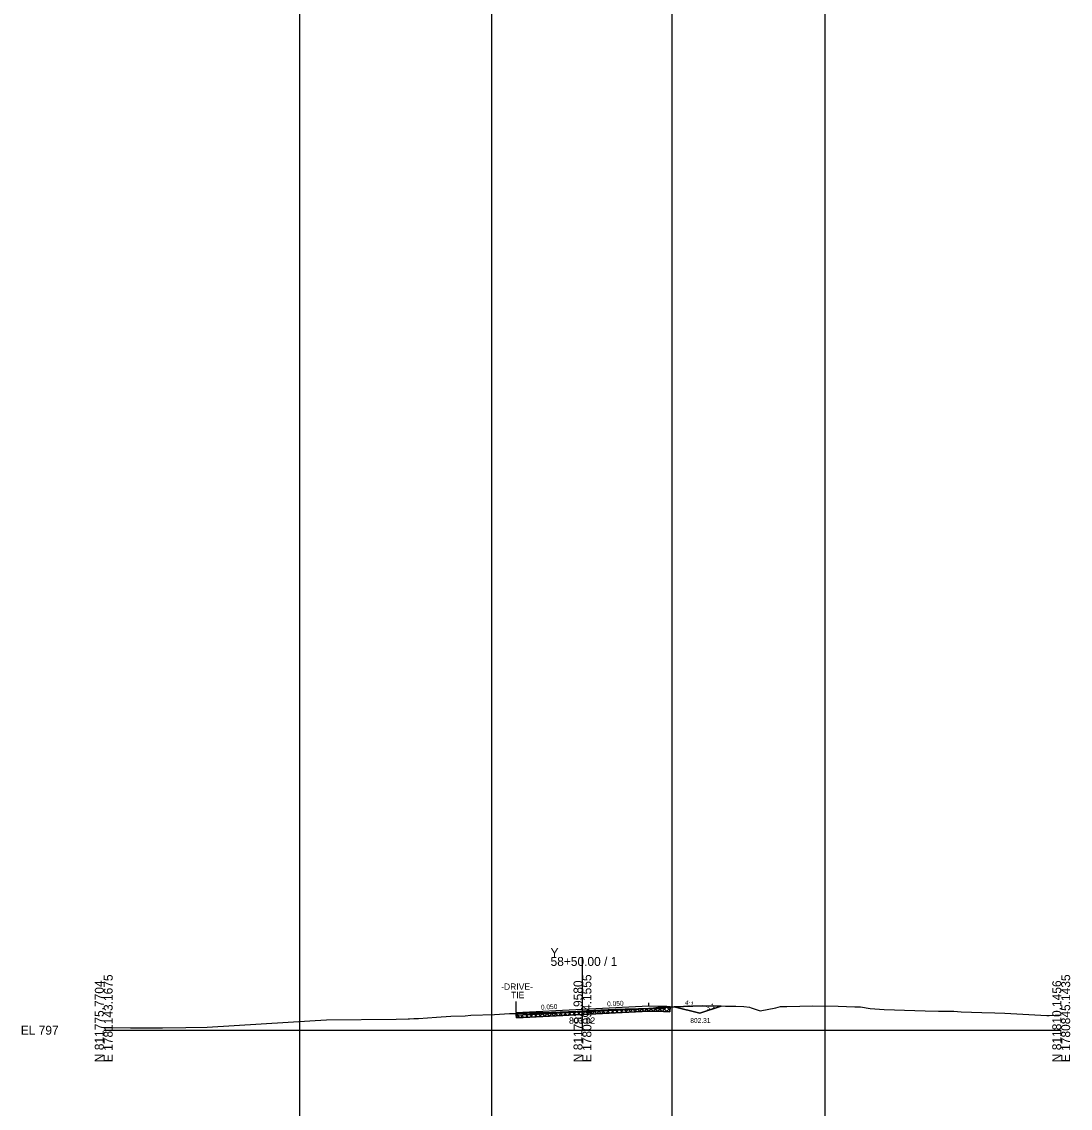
# Model space of a CAD drawing. Extents: x -12583 to 5303, y -44 to 25667.
# Drawn here: x 3974.3 to 4302.8, y 8975.6 to 9315.9 of the extents above; entities that cross this region are included whole.
import ezdxf

# ---------------------------------------------------------------- set-up
doc = ezdxf.new("R2010")
doc.units = 0
for name, color, linetype in [('Exist Cross Section Cell', 7, 'Continuous'), ('Exist XS Center Line Elevation Label', 7, 'Continuous'), ('Exist XS Ground Line', 7, 'Continuous'), ('Prop CMT Shallow Undercut', 7, 'Continuous'), ('Prop XS Ditch Slope Text', 7, 'Continuous'), ('Prop XS Ditch Standard Text', 7, 'Continuous'), ('Prop XS Dump Level', 7, 'Continuous'), ('Prop XS Earthwork Shape', 7, 'Continuous'), ('Prop XS Earthwork Undercut', 7, 'Continuous'), ('Prop XS EOT Tick Mark', 7, 'Continuous'), ('Prop XS Exc Vertical Line 1', 7, 'Continuous'), ('Prop XS Exc Vertical Line 2', 7, 'Continuous'), ('Prop XS Finish Grade', 7, 'Continuous'), ('Prop XS Finish Grade Earthwork', 7, 'Continuous'), ('Prop XS Finish Grade Paved Shoulder', 7, 'Continuous'), ('Prop XS Finish Grade Pavement', 7, 'Continuous'), ('Prop XS Label Text', 7, 'Continuous'), ('Prop XS Pvmt Edge Slope', 7, 'Continuous'), ('Prop XS SE Text', 7, 'Continuous'), ('Prop XS Side Slope Text', 7, 'Continuous'), ('Prop XS Subgrade Earthwork', 7, 'Continuous'), ('Prop XS Undercut Exc Hatch', 7, 'Continuous'), ('Scratch_Level_1', 7, 'Continuous'), ('Scratch_Level_2', 7, 'Continuous'), ('Scratch_Level_3', 7, 'Continuous'), ('Scratch_Level_4', 7, 'Continuous'), ('Scratch_Level_6', 7, 'Continuous')]:
    doc.layers.add(name, color=color, linetype=linetype)

msp = doc.modelspace()

# ---------------------------------------------------------------- linework, layer by layer
at = {"layer": 'Exist Cross Section Cell'}
for p, q in [((4150, 9000), (4150, 9022.94)), ((4000, 9000), (4150, 9000)), ((4150, 9000), (4300, 9000))]:
    msp.add_line(p, q, dxfattribs=at)
at = {"layer": 'Exist XS Ground Line'}
for p, q in [((4140.33, 9005.57), (4148.34, 9005.9)), ((4148.34, 9005.9), (4150, 9006.02)), ((4150, 9006.02), (4151.27, 9006.11)), ((4151.27, 9006.11), (4160.25, 9006.46)), ((4160.25, 9006.46), (4162.27, 9006.51)), ((4162.27, 9006.51), (4163.41, 9006.62)), ((4163.41, 9006.62), (4169.21, 9006.71)), ((4169.21, 9006.71), (4171.58, 9006.85)), ((4171.58, 9006.85), (4174.96, 9007.28)), ((4174.96, 9007.28), (4176.48, 9007.46)), ((4176.48, 9007.46), (4176.52, 9007.22)), ((4176.52, 9007.22), (4178.69, 9007.3)), ((4178.69, 9007.3), (4187.52, 9007.61)), ((4187.52, 9007.61), (4194.8, 9007.55)), ((4194.8, 9007.55), (4198.09, 9007.5)), ((4198.09, 9007.5), (4200.56, 9007.4)), ((4200.56, 9007.4), (4202.3, 9007.24)), ((4202.3, 9007.24), (4202.82, 9007.03)), ((4202.82, 9007.03), (4205.63, 9006.07)), ((4205.63, 9006.07), (4210.54, 9007.05)), ((4210.54, 9007.05), (4212.06, 9007.42)), ((4212.06, 9007.42), (4214.06, 9007.45)), ((4214.06, 9007.45), (4222.22, 9007.65)), ((4222.22, 9007.65), (4230.1, 9007.54)), ((4230.1, 9007.54), (4235.31, 9007.33)), ((4235.31, 9007.33), (4237.16, 9007.31)), ((4237.16, 9007.31), (4240.1, 9006.85)), ((4240.1, 9006.85), (4244.56, 9006.52)), ((4244.56, 9006.52), (4254.13, 9006.21)), ((4254.13, 9006.21), (4257.35, 9006.04)), ((4257.35, 9006.04), (4261.58, 9005.93)), ((4261.58, 9005.93), (4266.38, 9006.02)), ((4266.38, 9006.02), (4268.61, 9005.81)), ((4268.61, 9005.81), (4275.14, 9005.59)), ((4032.37, 9000.92), (4066.24, 9003.07)), ((4066.24, 9003.07), (4069.75, 9003.24)), ((4069.75, 9003.24), (4091.59, 9003.52)), ((4091.59, 9003.52), (4095.41, 9003.57)), ((4095.41, 9003.57), (4095.81, 9003.59)), ((4095.81, 9003.59), (4097.14, 9003.65)), ((4097.14, 9003.65), (4098.59, 9003.71)), ((4098.59, 9003.71), (4104.23, 9004.13)), ((4104.23, 9004.13), (4108.74, 9004.41)), ((4108.74, 9004.41), (4113.23, 9004.51)), ((4113.23, 9004.51), (4114.98, 9004.67)), ((4114.98, 9004.67), (4122.4, 9004.93)), ((4122.4, 9004.93), (4123.96, 9005)), ((4123.96, 9005), (4127.14, 9005.21)), ((4127.14, 9005.21), (4129.88, 9005.23)), ((4129.88, 9005.23), (4135.52, 9005.43)), ((4135.52, 9005.43), (4140.33, 9005.57)), ((4275.14, 9005.59), (4279.21, 9005.49)), ((4279.21, 9005.49), (4282.32, 9005.34)), ((4282.32, 9005.34), (4295.49, 9004.62)), ((4295.49, 9004.62), (4295.94, 9004.62)), ((4295.94, 9004.62), (4296.27, 9004.61)), ((4296.27, 9004.61), (4300, 9004.83)), ((4000, 9000.84), (4008.37, 9000.75)), ((4008.37, 9000.75), (4016.58, 9000.75)), ((4016.58, 9000.75), (4017.64, 9000.74)), ((4017.64, 9000.74), (4018.45, 9000.75)), ((4018.45, 9000.75), (4025.75, 9000.84)), ((4025.75, 9000.84), (4032.37, 9000.92))]:
    msp.add_line(p, q, dxfattribs=at)
at = {"layer": 'Prop CMT Shallow Undercut'}
msp.add_lwpolyline([(4176.18, 9007.43), (4176.48, 9007.46), (4176.52, 9007.22), (4177.45, 9007.25), (4177.35, 9005.78), (4175.38, 9005.92), (4170.77, 9005.97), (4150.05, 9004.93), (4129.3, 9003.89), (4129.25, 9004.77), (4150.04, 9005.8), (4167.58, 9006.68), (4169.21, 9006.71), (4171.38, 9006.84), (4175.55, 9006.79)], close=True, dxfattribs=at)
at = {"layer": 'Prop XS Dump Level'}
for p, q in [((4129.25, 9005.56), (4150, 9006.6)), ((4150, 9006.6), (4170.75, 9007.63))]:
    msp.add_line(p, q, dxfattribs=at)
at = {"layer": 'Prop XS Earthwork Shape'}
for points in [[(4151.27, 9006.11), (4160.25, 9006.46), (4162.27, 9006.51), (4163.41, 9006.62), (4167.58, 9006.68), (4150.04, 9005.8), (4129.25, 9004.77), (4129.25, 9005.22), (4129.88, 9005.23), (4135.52, 9005.43), (4140.33, 9005.57), (4148.34, 9005.9), (4150, 9006.02)], [(4167.58, 9006.68), (4169.21, 9006.71), (4171.38, 9006.84), (4170.77, 9006.84)], [(4171.38, 9006.84), (4175.55, 9006.79), (4176.18, 9007.43), (4174.96, 9007.28), (4171.58, 9006.85)], [(4176.18, 9007.43), (4176.24, 9007.49), (4176.48, 9007.46)], [(4178.75, 9007.31), (4178.78, 9007.31), (4178.69, 9007.3), (4176.52, 9007.22), (4176.48, 9007.46)], [(4178.78, 9007.31), (4186.75, 9005.31), (4193.5, 9007.56), (4187.52, 9007.61)]]:
    msp.add_lwpolyline(points, close=True, dxfattribs=at)
at = {"layer": 'Prop XS Earthwork Undercut'}
for p, q in [((4129.25, 9005.56), (4129.25, 9008.99)), ((4170.77, 9005.97), (4150.05, 9004.93)), ((4170.77, 9005.97), (4175.38, 9005.92)), ((4175.38, 9005.92), (4177.35, 9005.78)), ((4177.45, 9007.25), (4177.35, 9005.78)), ((4129.26, 9004.77), (4129.3, 9003.89)), ((4150.05, 9004.93), (4129.3, 9003.89))]:
    msp.add_line(p, q, dxfattribs=at)
at = {"layer": 'Prop XS EOT Tick Mark'}
for p, q in [((4129.25, 9005.56), (4129.25, 9006.56)), ((4170.75, 9007.63), (4170.75, 9008.63))]:
    msp.add_line(p, q, dxfattribs=at)
at = {"layer": 'Prop XS Exc Vertical Line 1'}
msp.add_line((4121.63, 6478.95), (4121.63, 9656.26), dxfattribs=at)
at = {"layer": 'Prop XS Exc Vertical Line 2'}
msp.add_line((4178.09, 6478.95), (4178.09, 9642.11), dxfattribs=at)
at = {"layer": 'Prop XS Finish Grade'}
msp.add_line((4174.75, 9007.59), (4176.24, 9007.49), dxfattribs=at)
at = {"layer": 'Prop XS Finish Grade Earthwork'}
for p, q in [((4176.24, 9007.49), (4178.75, 9007.31)), ((4178.75, 9007.31), (4186.75, 9005.31)), ((4186.75, 9005.31), (4193.5, 9007.56))]:
    msp.add_line(p, q, dxfattribs=at)
at = {"layer": 'Prop XS Finish Grade Paved Shoulder'}
msp.add_line((4170.75, 9007.63), (4174.75, 9007.59), dxfattribs=at)
at = {"layer": 'Prop XS Finish Grade Pavement'}
for p, q in [((4129.25, 9005.56), (4150, 9006.6)), ((4150, 9006.6), (4170.75, 9007.63)), ((4129.25, 9005.56), (4129.25, 9005.22))]:
    msp.add_line(p, q, dxfattribs=at)
at = {"layer": 'Prop XS Pvmt Edge Slope'}
msp.add_line((4174.75, 9007.59), (4175.55, 9006.79), dxfattribs=at)
at = {"layer": 'Prop XS Subgrade Earthwork'}
for p, q in [((4129.25, 9004.77), (4150.04, 9005.8)), ((4150.04, 9005.8), (4170.77, 9006.84)), ((4170.77, 9006.84), (4175.55, 9006.79)), ((4175.55, 9006.79), (4176.24, 9007.49)), ((4129.25, 9004.77), (4129.25, 9005.22))]:
    msp.add_line(p, q, dxfattribs=at)
at = {"layer": 'Prop XS Undercut Exc Hatch'}
for p, q in [((4147.78, 9004.82), (4146.95, 9005.65)), ((4146.99, 9004.78), (4147.92, 9005.7)), ((4149.13, 9004.88), (4148.29, 9005.72)), ((4148.48, 9004.85), (4149.4, 9005.77)), ((4150.47, 9004.95), (4149.64, 9005.79)), ((4149.97, 9004.93), (4150.89, 9005.85)), ((4151.82, 9005.02), (4150.99, 9005.85)), ((4151.46, 9005), (4152.38, 9005.92)), ((4153.17, 9005.09), (4152.33, 9005.92)), ((4152.95, 9005.08), (4153.87, 9006)), ((4154.51, 9005.15), (4153.68, 9005.99)), ((4154.44, 9005.15), (4155.36, 9006.07)), ((4155.86, 9005.22), (4155.03, 9006.05)), ((4155.93, 9005.22), (4156.85, 9006.15)), ((4157.21, 9005.29), (4156.37, 9006.12)), ((4157.42, 9005.3), (4158.34, 9006.22)), ((4158.55, 9005.36), (4157.72, 9006.19)), ((4158.9, 9005.37), (4159.83, 9006.29)), ((4159.9, 9005.42), (4159.07, 9006.26)), ((4160.39, 9005.45), (4161.31, 9006.37)), ((4161.25, 9005.49), (4160.41, 9006.32)), ((4162.6, 9005.56), (4161.76, 9006.39)), ((4161.88, 9005.52), (4162.8, 9006.44)), ((4163.94, 9005.62), (4163.11, 9006.46)), ((4163.37, 9005.6), (4164.29, 9006.52)), ((4165.29, 9005.69), (4164.46, 9006.53)), ((4164.86, 9005.67), (4165.78, 9006.59)), ((4166.64, 9005.76), (4165.8, 9006.59)), ((4166.35, 9005.75), (4167.27, 9006.67)), ((4167.98, 9005.83), (4167.15, 9006.66)), ((4167.84, 9005.82), (4168.72, 9006.7)), ((4169.33, 9005.89), (4168.53, 9006.7)), ((4169.32, 9005.89), (4170.2, 9006.77)), ((4170.68, 9005.96), (4169.89, 9006.75)), ((4170.81, 9005.97), (4171.68, 9006.83)), ((4172.1, 9005.95), (4171.23, 9006.83)), ((4172.21, 9005.95), (4173.08, 9006.82)), ((4173.53, 9005.94), (4172.64, 9006.82)), ((4173.61, 9005.94), (4174.48, 9006.8)), ((4174.96, 9005.92), (4174.07, 9006.81)), ((4175.01, 9005.92), (4176.49, 9007.4)), ((4176.45, 9005.85), (4175.5, 9006.79)), ((4177.39, 9006.32), (4176.27, 9007.44)), ((4176.35, 9005.85), (4177.43, 9006.93)), ((4129.29, 9004.05), (4130.05, 9004.81)), ((4130.27, 9003.94), (4129.44, 9004.77)), ((4130.62, 9003.96), (4131.54, 9004.88)), ((4131.62, 9004.01), (4130.78, 9004.84)), ((4132.11, 9004.03), (4133.03, 9004.95)), ((4132.96, 9004.08), (4132.13, 9004.91)), ((4134.31, 9004.14), (4133.48, 9004.98)), ((4133.6, 9004.11), (4134.52, 9005.03)), ((4135.66, 9004.21), (4134.82, 9005.04)), ((4135.09, 9004.18), (4136.01, 9005.1)), ((4137, 9004.28), (4136.17, 9005.11)), ((4136.57, 9004.26), (4137.5, 9005.18)), ((4138.35, 9004.35), (4137.52, 9005.18)), ((4138.06, 9004.33), (4138.98, 9005.25)), ((4139.7, 9004.41), (4138.86, 9005.25)), ((4139.55, 9004.41), (4140.47, 9005.33)), ((4141.05, 9004.48), (4140.21, 9005.31)), ((4141.04, 9004.48), (4141.96, 9005.4)), ((4142.39, 9004.55), (4141.56, 9005.38)), ((4142.53, 9004.55), (4143.45, 9005.48)), ((4143.74, 9004.61), (4142.91, 9005.45)), ((4144.02, 9004.63), (4144.94, 9005.55)), ((4145.09, 9004.68), (4144.25, 9005.52)), ((4145.51, 9004.7), (4146.43, 9005.62)), ((4146.43, 9004.75), (4145.6, 9005.58))]:
    msp.add_line(p, q, dxfattribs=at)
at = {"layer": 'Scratch_Level_1'}
msp.add_line((4061.32, 9572.59), (4061.32, 6980.12), dxfattribs=at)
at = {"layer": 'Scratch_Level_2'}
msp.add_line((4225.92, 9572.59), (4225.92, 6980.12), dxfattribs=at)
at = {"layer": 'Scratch_Level_3'}
for points in [[(4150.04, 9005.8), (4167.58, 9006.68), (4163.41, 9006.62), (4162.27, 9006.51), (4160.25, 9006.46), (4151.27, 9006.11), (4150, 9006.02), (4148.34, 9005.9), (4140.33, 9005.57), (4135.52, 9005.43), (4129.88, 9005.23), (4129.25, 9005.22), (4129.25, 9004.77)], [(4171.38, 9006.84), (4171.58, 9006.85), (4174.96, 9007.28), (4176.18, 9007.43), (4175.55, 9006.79)]]:
    msp.add_lwpolyline(points, close=True, dxfattribs=at)
at = {"layer": 'Scratch_Level_4'}
for points in [[(4160.25, 9006.46), (4162.27, 9006.51), (4163.41, 9006.62), (4167.58, 9006.68), (4150.04, 9005.8), (4129.25, 9004.77), (4129.25, 9005.22), (4129.88, 9005.23), (4135.52, 9005.43), (4140.33, 9005.57), (4148.34, 9005.9), (4150, 9006.02), (4151.27, 9006.11)], [(4171.38, 9006.84), (4175.55, 9006.79), (4176.18, 9007.43), (4174.96, 9007.28), (4171.58, 9006.85)], [(4178.78, 9007.31), (4187.52, 9007.61), (4193.5, 9007.56), (4186.75, 9005.31)]]:
    msp.add_lwpolyline(points, close=True, dxfattribs=at)
at = {"layer": 'Scratch_Level_6'}
for points in [[(4150.05, 9004.93), (4129.3, 9003.89), (4129.25, 9004.77), (4150.04, 9005.8), (4167.58, 9006.68), (4169.21, 9006.71), (4171.38, 9006.84), (4175.55, 9006.79), (4176.18, 9007.43), (4176.48, 9007.46), (4176.52, 9007.22), (4177.45, 9007.25), (4177.35, 9005.78), (4175.38, 9005.92), (4170.77, 9005.97)], [(4170.77, 9005.97), (4175.38, 9005.92), (4177.35, 9005.78), (4177.45, 9007.25), (4176.52, 9007.22), (4176.48, 9007.46), (4176.18, 9007.43), (4175.55, 9006.79), (4171.38, 9006.84), (4169.21, 9006.71), (4167.58, 9006.68), (4150.04, 9005.8), (4129.25, 9004.77), (4129.3, 9003.89), (4150.05, 9004.93)], [(4170.77, 9006.84), (4171.38, 9006.84), (4169.21, 9006.71), (4167.58, 9006.68)], [(4170.77, 9006.84), (4171.38, 9006.84), (4169.21, 9006.71), (4167.58, 9006.68)]]:
    msp.add_lwpolyline(points, close=True, dxfattribs=at)

# ---------------------------------------------------------------- texts
at = {"layer": 'Exist Cross Section Cell'}
for s, p in [('Y', (4140, 9022.94)), ('58+50.00 / 1', (4140, 9020.14)), ('EL 797', (3974, 8998.6))]:
    msp.add_text(s, height=2.8, dxfattribs=at).set_placement(p)
for s, p in [('E 1781143.1675', (4002.8, 8990)), ('E 1780994.1555', (4152.8, 8990)), ('E 1780845.1435', (4302.8, 8990)), ('N 811775.7704', (4000, 8990)), ('N 811792.9580', (4150, 8990)), ('N 811810.1456', (4300, 8990))]:
    msp.add_text(s, height=2.8, rotation=90, dxfattribs=at).set_placement(p)
at = {"layer": 'Exist XS Center Line Elevation Label'}
msp.add_text('803.02', height=2, dxfattribs=at).set_placement((4145.79, 9002.02))
at = {"layer": 'Prop XS Ditch Slope Text'}
msp.add_text('4:1', height=1.5, rotation=345.9638, dxfattribs=at).set_placement((4181.94, 9008.06))
at = {"layer": 'Prop XS Ditch Standard Text'}
msp.add_text('802.31', height=1.5, dxfattribs=at).set_placement((4183.78, 9002.31))
at = {"layer": 'Prop XS Dump Level'}
msp.add_text('Case2', height=0.04, dxfattribs=at).set_placement((4178.75, 9007.27))
at = {"layer": 'Prop XS Label Text'}
for s, p in [('-DRIVE-', (4124.52, 9012.66)), ('TIE', (4127.63, 9010.04))]:
    msp.add_text(s, height=2, dxfattribs=at).set_placement(p)
at = {"layer": 'Prop XS SE Text'}
for p in [(4157.75, 9007.48), (4137, 9006.45)]:
    msp.add_text('0.050', height=1.5, rotation=2.8624, dxfattribs=at).set_placement(p)
at = {"layer": 'Prop XS Side Slope Text'}
msp.add_text('3:1', height=1.5, rotation=19.6191, dxfattribs=at).set_placement((4188.98, 9006.18))

doc.saveas('drawing.dxf')
